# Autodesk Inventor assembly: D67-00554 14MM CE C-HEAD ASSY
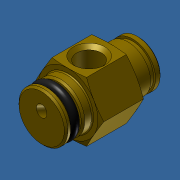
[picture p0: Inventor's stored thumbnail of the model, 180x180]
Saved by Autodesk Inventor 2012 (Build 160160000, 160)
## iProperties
Created: 2013-10
Part Number: D67-00554 14MM CE C-HEAD ASSY
Document SubType Name: Assembly
Designer: Admin
Author: Admin
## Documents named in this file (3)
- C:\Andys Backup Data\ANDY'S INVENTOR\INVENTOR LIBRARIES\PARTS LIBRARY\HYDRAULIC VERTICAL ADJUSTMENT\27.9001Telescoping Twin Leg System\SUBCOMPONENTS\CEx30 cylinder\D67-00554 14MM CE C-HEAD ASSY.iam
- C:\Andys Backup Data\ANDY'S INVENTOR\INVENTOR LIBRARIES\PARTS LIBRARY\HYDRAULIC VERTICAL ADJUSTMENT\27.9001Telescoping Twin Leg System\SUBCOMPONENTS\CEx30 cylinder\667-00554 14MM CE CONNECTING HEAD.ipt
- C:\Andys Backup Data\ANDY'S INVENTOR\INVENTOR LIBRARIES\PARTS LIBRARY\HYDRAULIC VERTICAL ADJUSTMENT\27.9001Telescoping Twin Leg System\SUBCOMPONENTS\CEx30 cylinder\H60-0004 O-RINGS_660-00026.ipt
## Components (2 placed, 2 different names)
1. 667-00554 14MM CE CONNECTING HEAD:1
2. H60-0004 O-RINGS_660-00026:1
